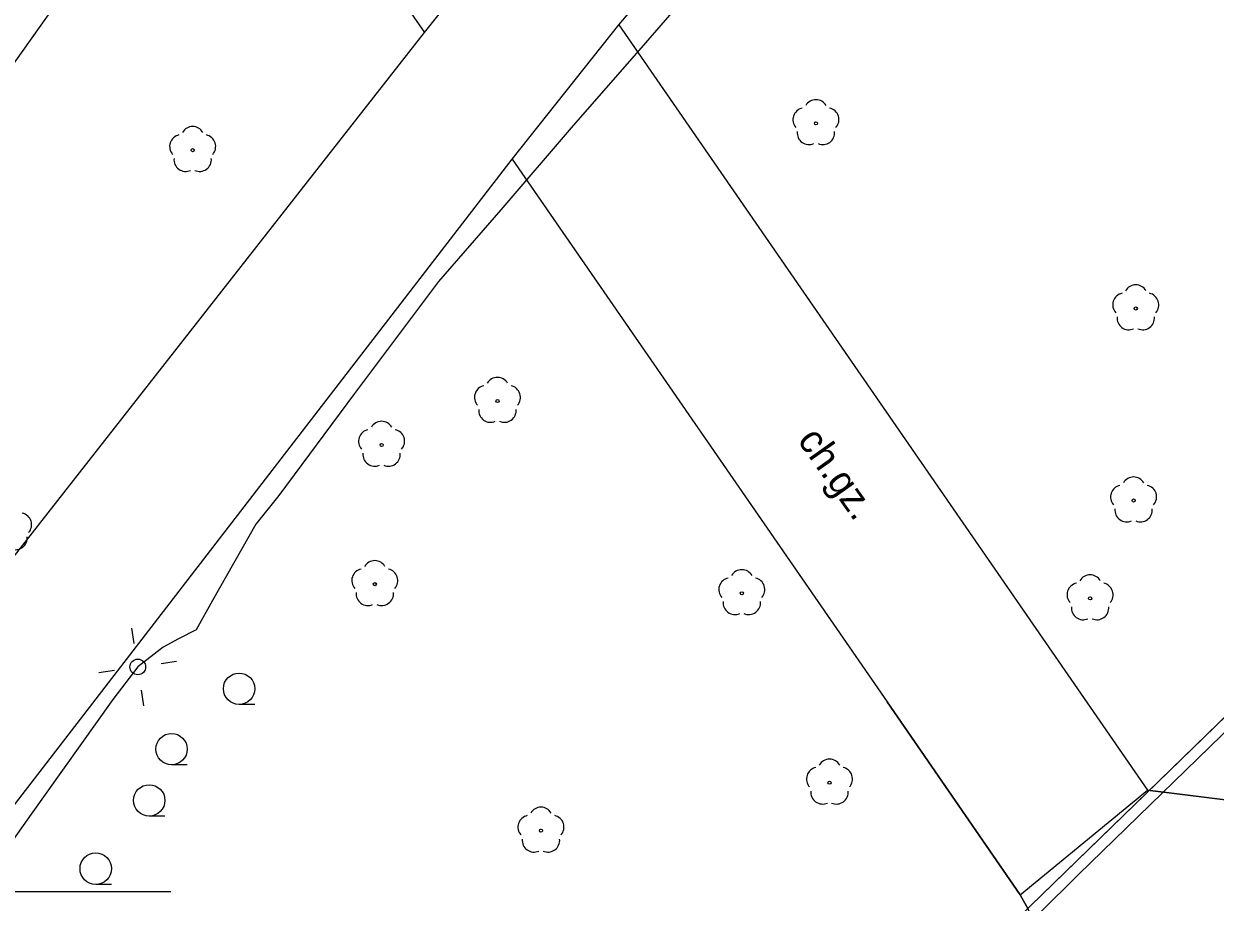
# Model space of a CAD drawing. Extents: x 6434771 to 6436222, y 5663454 to 5664782.
# Drawn here: x 6435500.32 to 6435538.2, y 5663799.67 to 5663827.6 of the extents above; entities that cross this region are included whole.
import ezdxf

# ---------------------------------------------------------------- set-up
doc = ezdxf.new("R2010")
doc.units = 0
for name, color, linetype in [('Warstwa 1', 7, 'Continuous'), ('Warstwa 11', 7, 'Continuous'), ('Warstwa 12', 7, 'Continuous'), ('Warstwa 2', 7, 'Continuous'), ('Warstwa 4', 7, 'Continuous'), ('Warstwa 5', 7, 'Continuous'), ('Warstwa 6', 7, 'Continuous'), ('Warstwa 63', 7, 'Continuous'), ('Warstwa 8', 7, 'Continuous'), ('Warstwa 9', 7, 'Continuous')]:
    doc.layers.add(name, color=color, linetype=linetype)

msp = doc.modelspace()

# ---------------------------------------------------------------- linework, layer by layer
at = {"layer": 'Warstwa 1'}
msp.add_line((6435527.892, 5663795.248), (6435570.992, 5663837.121), dxfattribs=at)
msp.add_line((6435527.892, 5663795.248), (6435570.992, 5663837.121), dxfattribs=at)
at = {"layer": 'Warstwa 11'}
for centre in [(6435525.51, 5663824.44), (6435505.692, 5663823.588), (6435535.679, 5663818.553), (6435515.383, 5663815.61), (6435511.699, 5663814.214), (6435535.61, 5663812.446), (6435511.483, 5663809.785), (6435523.153, 5663809.497), (6435534.227, 5663809.333), (6435525.941, 5663803.472), (6435516.767, 5663801.945)]:
    msp.add_circle(centre, 0.05, dxfattribs=at)
for centre, start, end in [((6435525.51, 5663824.815), 30.1471, 149.8529), ((6435525.153, 5663824.556), 102.1471, 221.8529), ((6435525.867, 5663824.556), 318.1471, 77.8529), ((6435505.692, 5663823.963), 30.1471, 149.8529), ((6435525.29, 5663824.137), 174.1471, 293.8529), ((6435525.73, 5663824.137), 246.1471, 5.8529), ((6435505.335, 5663823.704), 102.1471, 221.8529), ((6435506.049, 5663823.704), 318.1471, 77.8529), ((6435505.472, 5663823.285), 174.1471, 293.8529), ((6435505.912, 5663823.285), 246.1471, 5.8529), ((6435535.679, 5663818.928), 30.1471, 149.8529), ((6435535.322, 5663818.669), 102.1471, 221.8529), ((6435536.036, 5663818.669), 318.1471, 77.8529), ((6435535.459, 5663818.25), 174.1471, 293.8529), ((6435535.899, 5663818.25), 246.1471, 5.8529), ((6435515.383, 5663815.985), 30.1471, 149.8529), ((6435515.026, 5663815.726), 102.1471, 221.8529), ((6435515.74, 5663815.726), 318.1471, 77.8529), ((6435515.163, 5663815.307), 174.1471, 293.8529), ((6435515.603, 5663815.307), 246.1471, 5.8529), ((6435511.342, 5663814.33), 102.1471, 221.8529), ((6435511.699, 5663814.589), 30.1471, 149.8529), ((6435512.056, 5663814.33), 318.1471, 77.8529), ((6435511.479, 5663813.911), 174.1471, 293.8529), ((6435511.919, 5663813.911), 246.1471, 5.8529), ((6435535.61, 5663812.821), 30.1471, 149.8529), ((6435535.253, 5663812.562), 102.1471, 221.8529), ((6435535.967, 5663812.562), 318.1471, 77.8529), ((6435535.39, 5663812.143), 174.1471, 293.8529), ((6435535.83, 5663812.143), 246.1471, 5.8529), ((6435500.197, 5663811.676), 318.1471, 77.8529), ((6435500.06, 5663811.257), 246.1471, 5.8529), ((6435511.483, 5663810.16), 30.1471, 149.8529), ((6435511.126, 5663809.901), 102.1471, 221.8529), ((6435511.84, 5663809.901), 318.1471, 77.8529), ((6435523.153, 5663809.872), 30.1471, 149.8529), ((6435522.796, 5663809.613), 102.1471, 221.8529), ((6435523.51, 5663809.613), 318.1471, 77.8529), ((6435533.87, 5663809.449), 102.1471, 221.8529), ((6435534.227, 5663809.708), 30.1471, 149.8529), ((6435534.584, 5663809.449), 318.1471, 77.8529), ((6435511.263, 5663809.482), 174.1471, 293.8529), ((6435511.703, 5663809.482), 246.1471, 5.8529), ((6435522.933, 5663809.194), 174.1471, 293.8529), ((6435523.373, 5663809.194), 246.1471, 5.8529), ((6435534.007, 5663809.03), 174.1471, 293.8529), ((6435534.447, 5663809.03), 246.1471, 5.8529), ((6435525.941, 5663803.847), 30.1471, 149.8529), ((6435525.584, 5663803.588), 102.1471, 221.8529), ((6435526.298, 5663803.588), 318.1471, 77.8529), ((6435525.721, 5663803.169), 174.1471, 293.8529), ((6435526.161, 5663803.169), 246.1471, 5.8529), ((6435516.767, 5663802.32), 30.1471, 149.8529), ((6435516.41, 5663802.061), 102.1471, 221.8529), ((6435517.124, 5663802.061), 318.1471, 77.8529), ((6435516.547, 5663801.642), 174.1471, 293.8529), ((6435516.987, 5663801.642), 246.1471, 5.8529)]:
    msp.add_arc(centre, 0.375, start, end, dxfattribs=at)
at = {"layer": 'Warstwa 12'}
for points in [[(6435465.145, 5663779.301), (6435479.98, 5663798.908), (6435484.2, 5663804.668), (6435488.278, 5663809.701), (6435494.681, 5663818.854), (6435504.116, 5663832.141), (6435514.059, 5663844.527), (6435522.997, 5663857.62), (6435545.493, 5663888.796), (6435569.737, 5663922.271), (6435582.719, 5663940.386)], [(6435528.881, 5663795.616), (6435533.856, 5663800.554), (6435539.551, 5663806.088), (6435542.138, 5663808.709), (6435546.507, 5663812.75), (6435551.524, 5663817.65), (6435564.609, 5663830.373), (6435568.753, 5663834.665), (6435569.277, 5663834.98), (6435570.334, 5663835.827), (6435571.826, 5663837.072), (6435574.267, 5663839.086), (6435576.763, 5663841.179), (6435580.251, 5663844.052), (6435582.992, 5663846.385), (6435586.22, 5663849.061)], [(6435522.326, 5663829.581), (6435520.092, 5663827.001), (6435517.728, 5663824.299), (6435515.494, 5663821.692), (6435513.506, 5663819.405), (6435510.837, 5663815.851), (6435508.434, 5663812.601), (6435507.698, 5663811.696), (6435506.327, 5663809.266), (6435505.804, 5663808.333), (6435505.237, 5663808.043), (6435504.751, 5663807.781), (6435503.947, 5663807.154), (6435503.156, 5663806.122), (6435500.561, 5663802.471), (6435497.123, 5663797.631)]]:
    msp.add_lwpolyline(points, dxfattribs=at)
at = {"layer": 'Warstwa 2'}
msp.add_circle((6435503.947, 5663807.154), 0.25, dxfattribs=at)
at = {"layer": 'Warstwa 4'}
for points in [[(6435503.835, 5663807.896), (6435503.76, 5663808.39)], [(6435504.689, 5663807.266), (6435505.183, 5663807.341)], [(6435503.205, 5663807.042), (6435502.711, 5663806.967)], [(6435504.059, 5663806.412), (6435504.134, 5663805.918)]]:
    msp.add_lwpolyline(points, dxfattribs=at)
at = {"layer": 'Warstwa 5'}
for p, q in [((6435519.241, 5663827.574), (6435535.839, 5663847.135)), ((6435519.241, 5663827.574), (6435536.049, 5663803.24)), ((6435536.049, 5663803.24), (6435539.954, 5663802.753))]:
    msp.add_line(p, q, dxfattribs=at)
at = {"layer": 'Warstwa 6'}
for p, q in [((6435507.67, 5663805.96), (6435507.17, 5663805.96)), ((6435505.52, 5663804.04), (6435505.02, 5663804.04)), ((6435504.81, 5663802.41), (6435504.31, 5663802.41)), ((6435503.11, 5663800.24), (6435502.61, 5663800.24))]:
    msp.add_line(p, q, dxfattribs=at)
for points in [[(6435497.48, 5663799.45), (6435506.7, 5663789.56), (6435508.43, 5663787.33), (6435509.75, 5663785.12), (6435510.77, 5663783.65), (6435512.59, 5663782.25), (6435514.22, 5663781.8), (6435527.892, 5663795.248), (6435570.992, 5663837.121), (6435586.939, 5663852.54), (6435599.429, 5663860.81), (6435608.979, 5663864.176), (6435617.268, 5663864.926), (6435627.619, 5663865.031), (6435640.832, 5663867.732), (6435649.164, 5663870.462), (6435662.228, 5663877.475)], [(6435662.228, 5663877.475), (6435649.164, 5663870.462), (6435640.832, 5663867.732), (6435627.619, 5663865.031), (6435617.268, 5663864.926), (6435608.979, 5663864.176), (6435599.429, 5663860.81), (6435586.939, 5663852.54), (6435570.992, 5663837.121), (6435527.892, 5663795.248)], [(6435583.508, 5663845.088), (6435582.732, 5663844.262), (6435578.347, 5663840.19), (6435575.766, 5663837.756), (6435572.445, 5663834.487), (6435568.337, 5663830.514), (6435563.878, 5663826.121), (6435558.354, 5663820.764), (6435553.861, 5663816.312), (6435548.462, 5663811.023), (6435544.479, 5663807.106), (6435540.739, 5663803.382), (6435539.954, 5663802.753), (6435536.049, 5663803.24)], [(6435532, 5663799.91), (6435527.77, 5663806.04)], [(6435531.12, 5663793.71), (6435531.495, 5663794.077), (6435531.828, 5663794.482), (6435532.114, 5663794.921), (6435532.351, 5663795.389), (6435532.536, 5663795.88), (6435532.666, 5663796.388), (6435532.739, 5663796.907), (6435532.756, 5663797.432), (6435532.715, 5663797.955), (6435532.618, 5663798.47), (6435532.465, 5663798.972), (6435532.258, 5663799.453), (6435532, 5663799.91)]]:
    msp.add_lwpolyline(points, dxfattribs=at)
for centre in [(6435507.17, 5663806.46), (6435505.02, 5663804.54), (6435504.31, 5663802.91), (6435502.61, 5663800.74)]:
    msp.add_circle(centre, 0.5, dxfattribs=at)
at = {"layer": 'Warstwa 63'}
msp.add_line((6435505, 5663800), (6435495, 5663800), dxfattribs=at)
at = {"layer": 'Warstwa 8'}
for p, q in [((6435532, 5663799.91), (6435536.049, 5663803.24)), ((6435536.049, 5663803.24), (6435539.954, 5663802.753)), ((6435532, 5663799.91), (6435532.258, 5663799.453))]:
    msp.add_line(p, q, dxfattribs=at)
at = {"layer": 'Warstwa 9'}
for p, q in [((6435519.241, 5663827.574), (6435535.839, 5663847.135)), ((6435505.42, 5663838.39), (6435513.06, 5663827.33)), ((6435513.06, 5663827.33), (6435514.37, 5663828.96)), ((6435513.06, 5663827.33), (6435514.37, 5663828.96)), ((6435495.3, 5663804.66), (6435513.06, 5663827.33)), ((6435515.849, 5663823.305), (6435519.241, 5663827.574)), ((6435515.849, 5663823.305), (6435519.241, 5663827.574)), ((6435519.241, 5663827.574), (6435536.049, 5663803.24)), ((6435497.357, 5663799.312), (6435515.849, 5663823.305)), ((6435515.849, 5663823.305), (6435527.77, 5663806.04)), ((6435527.77, 5663806.04), (6435532, 5663799.91)), ((6435532, 5663799.91), (6435536.049, 5663803.24))]:
    msp.add_line(p, q, dxfattribs=at)

# ---------------------------------------------------------------- texts
msp.add_text('ch.gz.', height=0.9, rotation=305.3235, dxfattribs=at).set_placement((6435524.899, 5663814.364))

doc.saveas('drawing.dxf')
